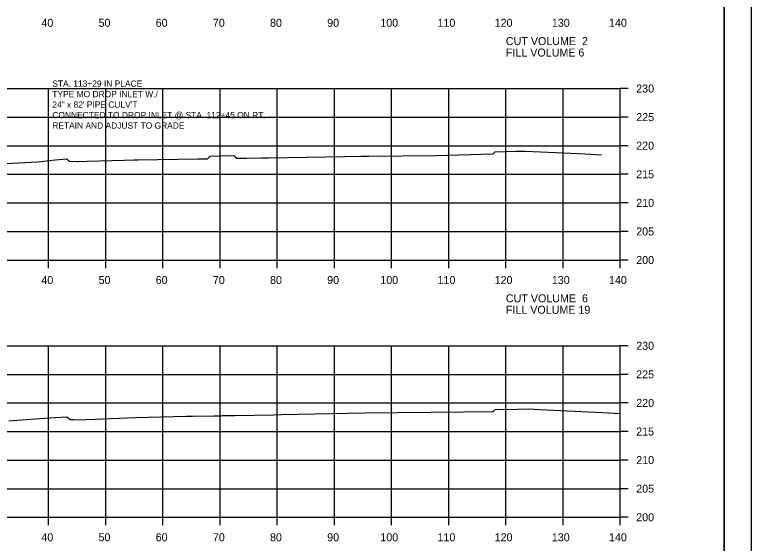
# Model space of a CAD drawing. Extents: x 1368968 to 1369915, y 377395 to 380381.
# Drawn here: x 1369785.9 to 1369914.7, y 378050.1 to 378142.6 of the extents above; entities that cross this region are included whole.
import ezdxf

# ---------------------------------------------------------------- set-up
doc = ezdxf.new("R2010")
doc.units = 0
for name, color, linetype in [('S_BREAKLINE_ANNOT', 7, 'Continuous'), ('S_BRIDGE', 7, 'Continuous'), ('S_BRIDGE_ANNOT', 7, 'Continuous'), ('S_CONTOUR_MINOR', 7, 'Continuous'), ('S_CTL_TABLE', 7, 'Continuous'), ('S_DITCHLINE_ANNOT', 7, 'Continuous'), ('S_DROP_INLET', 7, 'Continuous')]:
    doc.layers.add(name, color=color, linetype=linetype)

msp = doc.modelspace()

# ---------------------------------------------------------------- linework, layer by layer
at = {"layer": 'S_BREAKLINE_ANNOT'}
for p, q in [((1369891.78, 378099.69), (1369891.78, 378129.69)), ((1369893.18, 378129.69), (1369891.78, 378129.69)), ((1369893.18, 378124.69), (1369891.78, 378124.69)), ((1369893.18, 378119.69), (1369891.78, 378119.69)), ((1369893.18, 378114.69), (1369891.78, 378114.69)), ((1369893.18, 378109.69), (1369891.78, 378109.69)), ((1369893.18, 378104.69), (1369891.78, 378104.69)), ((1369611.78, 378099.69), (1369891.78, 378099.69)), ((1369791.78, 378098.29), (1369791.78, 378099.69)), ((1369801.78, 378098.29), (1369801.78, 378099.69)), ((1369811.78, 378098.29), (1369811.78, 378099.69)), ((1369821.78, 378098.29), (1369821.78, 378099.69)), ((1369831.78, 378098.29), (1369831.78, 378099.69)), ((1369841.78, 378098.29), (1369841.78, 378099.69)), ((1369851.78, 378098.29), (1369851.78, 378099.69)), ((1369861.78, 378098.29), (1369861.78, 378099.69)), ((1369871.78, 378098.29), (1369871.78, 378099.69)), ((1369881.78, 378098.29), (1369881.78, 378099.69)), ((1369891.78, 378098.29), (1369891.78, 378099.69)), ((1369893.18, 378099.69), (1369891.78, 378099.69)), ((1369891.78, 378054.69), (1369891.78, 378084.69)), ((1369893.18, 378084.69), (1369891.78, 378084.69)), ((1369893.18, 378079.69), (1369891.78, 378079.69)), ((1369893.18, 378074.69), (1369891.78, 378074.69)), ((1369893.18, 378069.69), (1369891.78, 378069.69)), ((1369893.18, 378064.69), (1369891.78, 378064.69)), ((1369893.18, 378059.69), (1369891.78, 378059.69)), ((1369611.78, 378054.69), (1369891.78, 378054.69)), ((1369791.78, 378053.29), (1369791.78, 378054.69)), ((1369801.78, 378053.29), (1369801.78, 378054.69)), ((1369811.78, 378053.29), (1369811.78, 378054.69)), ((1369821.78, 378053.29), (1369821.78, 378054.69)), ((1369831.78, 378053.29), (1369831.78, 378054.69)), ((1369841.78, 378053.29), (1369841.78, 378054.69)), ((1369851.78, 378053.29), (1369851.78, 378054.69)), ((1369861.78, 378053.29), (1369861.78, 378054.69)), ((1369871.78, 378053.29), (1369871.78, 378054.69)), ((1369881.78, 378053.29), (1369881.78, 378054.69)), ((1369891.78, 378053.29), (1369891.78, 378054.69)), ((1369893.18, 378054.69), (1369891.78, 378054.69))]:
    msp.add_line(p, q, dxfattribs=at)
at = {"layer": 'S_BRIDGE_ANNOT'}
msp.add_line((1369909.96, 378038.69), (1369909.96, 378244.15), dxfattribs=at)
at = {"layer": 'S_CTL_TABLE'}
for points in [[(1369784.22, 378116.55), (1369789.96, 378116.88), (1369792.92, 378117.21), (1369794.95, 378117.41), (1369795.01, 378117.36), (1369795.45, 378116.96), (1369796.76, 378116.93), (1369796.94, 378116.92), (1369798.47, 378116.97), (1369805.05, 378117.17), (1369806.78, 378117.22), (1369807.38, 378117.23), (1369817.95, 378117.41), (1369818.45, 378117.4), (1369819.59, 378117.42), (1369819.89, 378117.71), (1369820.05, 378117.88), (1369821.8, 378117.94), (1369824.17, 378117.98), (1369824.39, 378117.78), (1369824.7, 378117.5), (1369825.66, 378117.51), (1369826.38, 378117.51), (1369829.02, 378117.57), (1369830.17, 378117.58), (1369843.63, 378117.81), (1369846.43, 378117.88), (1369847.81, 378117.85), (1369859.47, 378118), (1369869.56, 378118.26), (1369869.74, 378118.42), (1369869.89, 378118.62), (1369873.54, 378118.71), (1369874.44, 378118.75), (1369875.12, 378118.73), (1369880.59, 378118.49), (1369885.57, 378118.28), (1369888.51, 378118.11)], [(1369784.85, 378071.58), (1369790.19, 378071.94), (1369792.95, 378072.16), (1369794.98, 378072.25), (1369795.29, 378072.01), (1369795.53, 378071.81), (1369796.19, 378071.79), (1369797.04, 378071.75), (1369802.68, 378071.99), (1369807, 378072.13), (1369815.82, 378072.36), (1369816.94, 378072.39), (1369820.72, 378072.45), (1369820.98, 378072.45), (1369821.96, 378072.46), (1369822.22, 378072.47), (1369823.22, 378072.47), (1369823.46, 378072.48), (1369824.36, 378072.48), (1369831.18, 378072.63), (1369832.54, 378072.65), (1369847.14, 378072.98), (1369864.39, 378073.15), (1369869.6, 378073.21), (1369869.66, 378073.29), (1369869.92, 378073.53), (1369873.76, 378073.61), (1369875.73, 378073.65), (1369877.74, 378073.57), (1369888.64, 378073), (1369891.78, 378072.86)]]:
    msp.add_lwpolyline(points, dxfattribs=at)
at = {"layer": 'S_DITCHLINE_ANNOT'}
for p, q in [((1369611.78, 378129.69), (1369891.78, 378129.69)), ((1369791.78, 378099.69), (1369791.78, 378129.69)), ((1369801.78, 378099.69), (1369801.78, 378129.69)), ((1369811.78, 378099.69), (1369811.78, 378129.69)), ((1369821.78, 378099.69), (1369821.78, 378129.69)), ((1369831.78, 378099.69), (1369831.78, 378129.69)), ((1369841.78, 378099.69), (1369841.78, 378129.69)), ((1369851.78, 378099.69), (1369851.78, 378129.69)), ((1369861.78, 378099.69), (1369861.78, 378129.69)), ((1369871.78, 378099.69), (1369871.78, 378129.69)), ((1369881.78, 378099.69), (1369881.78, 378129.69)), ((1369891.78, 378099.69), (1369891.78, 378129.69)), ((1369611.78, 378124.69), (1369891.78, 378124.69)), ((1369611.78, 378119.69), (1369891.78, 378119.69)), ((1369611.78, 378114.69), (1369891.78, 378114.69)), ((1369611.78, 378109.69), (1369891.78, 378109.69)), ((1369611.78, 378104.69), (1369891.78, 378104.69)), ((1369611.78, 378099.69), (1369891.78, 378099.69)), ((1369611.78, 378084.69), (1369891.78, 378084.69)), ((1369791.78, 378054.69), (1369791.78, 378084.69)), ((1369801.78, 378054.69), (1369801.78, 378084.69)), ((1369811.78, 378054.69), (1369811.78, 378084.69)), ((1369821.78, 378054.69), (1369821.78, 378084.69)), ((1369831.78, 378054.69), (1369831.78, 378084.69)), ((1369841.78, 378054.69), (1369841.78, 378084.69)), ((1369851.78, 378054.69), (1369851.78, 378084.69)), ((1369861.78, 378054.69), (1369861.78, 378084.69)), ((1369871.78, 378054.69), (1369871.78, 378084.69)), ((1369881.78, 378054.69), (1369881.78, 378084.69)), ((1369891.78, 378054.69), (1369891.78, 378084.69)), ((1369611.78, 378079.69), (1369891.78, 378079.69)), ((1369611.78, 378074.69), (1369891.78, 378074.69)), ((1369611.78, 378069.69), (1369891.78, 378069.69)), ((1369611.78, 378064.69), (1369891.78, 378064.69)), ((1369611.78, 378059.69), (1369891.78, 378059.69)), ((1369611.78, 378054.69), (1369891.78, 378054.69))]:
    msp.add_line(p, q, dxfattribs=at)
at = {"layer": 'S_DROP_INLET'}
for points in [[(1369581.37, 378248.05), (1369914.71, 378248.05), (1369914.71, 378034.71), (1369581.37, 378034.71)], [(1369827.7, 378244.15), (1369827.7, 378234.27), (1369863.43, 378234.27), (1369863.43, 378231.35), (1369886.63, 378231.35), (1369886.63, 378207.02), (1369909.96, 378207.02), (1369909.96, 378038.69), (1369593.78, 378038.69), (1369593.78, 378244.15)]]:
    msp.add_lwpolyline(points, close=True, dxfattribs=at)

# ---------------------------------------------------------------- texts
at = {"layer": 'S_BRIDGE'}
for s, p in [('40', (1369790.52, 378140.49)), ('50', (1369800.52, 378140.49)), ('60', (1369810.52, 378140.49)), ('70', (1369820.52, 378140.49)), ('80', (1369830.52, 378140.49)), ('90', (1369840.52, 378140.49)), ('100', (1369849.82, 378140.49)), ('110', (1369859.82, 378140.49)), ('120', (1369869.82, 378140.49)), ('130', (1369879.82, 378140.49)), ('140', (1369889.82, 378140.49)), ('CUT VOLUME  2', (1369871.78, 378137.29)), ('FILL VOLUME 6', (1369871.78, 378135.29)), ('230', (1369894.58, 378128.99)), ('225', (1369894.58, 378123.99)), ('220', (1369894.58, 378118.99)), ('215', (1369894.58, 378113.99)), ('210', (1369894.58, 378108.99)), ('205', (1369894.58, 378103.99)), ('200', (1369894.58, 378098.99)), ('40', (1369790.52, 378095.49)), ('50', (1369800.52, 378095.49)), ('60', (1369810.52, 378095.49)), ('70', (1369820.52, 378095.49)), ('80', (1369830.52, 378095.49)), ('90', (1369840.52, 378095.49)), ('100', (1369849.82, 378095.49)), ('110', (1369859.82, 378095.49)), ('120', (1369869.82, 378095.49)), ('130', (1369879.82, 378095.49)), ('140', (1369889.82, 378095.49)), ('CUT VOLUME  6', (1369871.78, 378092.29)), ('FILL VOLUME 19', (1369871.78, 378090.29)), ('230', (1369894.58, 378083.99)), ('225', (1369894.58, 378078.99)), ('220', (1369894.58, 378073.99)), ('215', (1369894.58, 378068.99)), ('210', (1369894.58, 378063.99)), ('205', (1369894.58, 378058.99)), ('200', (1369894.58, 378053.99)), ('40', (1369790.52, 378050.49)), ('50', (1369800.52, 378050.49)), ('60', (1369810.52, 378050.49)), ('70', (1369820.52, 378050.49)), ('80', (1369830.52, 378050.49)), ('90', (1369840.52, 378050.49)), ('100', (1369849.82, 378050.49)), ('110', (1369859.82, 378050.49)), ('120', (1369869.82, 378050.49)), ('130', (1369879.82, 378050.49)), ('140', (1369889.82, 378050.49))]:
    msp.add_text(s, height=1.4, dxfattribs=at).set_placement(p)
at = {"layer": 'S_CONTOUR_MINOR'}
for s, p in [('STA. 113+29 IN PLACE', (1369792.43, 378130)), ('TYPE MO DROP INLET W./ ', (1369792.43, 378128.17)), ('24" x 82\' PIPE CULV\'T ', (1369792.43, 378126.33)), ('CONNECTED TO DROP INLET @ STA. 112+45 ON RT. ', (1369792.43, 378124.5)), ('RETAIN AND ADJUST TO GRADE', (1369792.43, 378122.67))]:
    msp.add_text(s, height=1.1, dxfattribs=at).set_placement(p)

doc.saveas('drawing.dxf')
